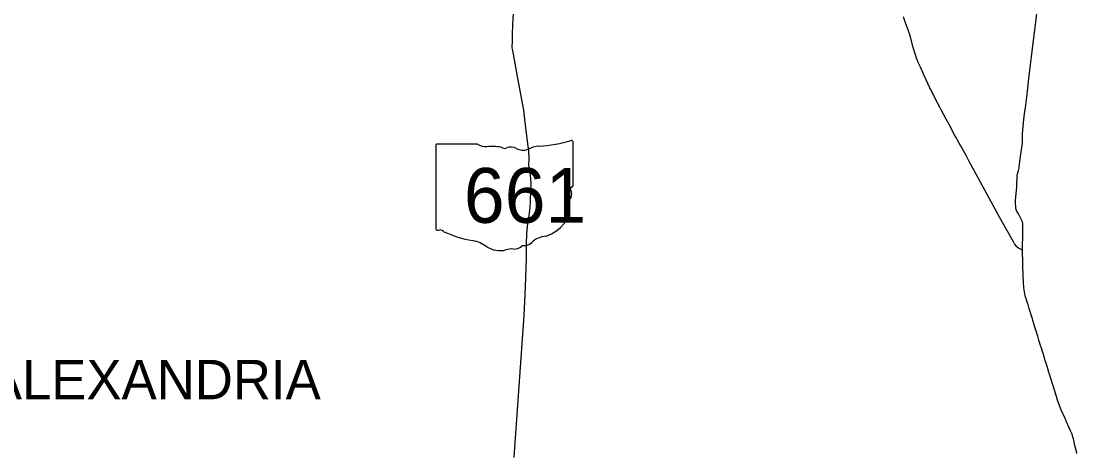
# Model space of a CAD drawing. Extents: x 1761803 to 2441803, y 509895 to 949895.
# Drawn here: x 1937717 to 1991282, y 855435 to 877258 of the extents above; entities that cross this region are included whole.
import ezdxf

# ---------------------------------------------------------------- set-up
doc = ezdxf.new("R2010")
doc.units = 0
for name, color, linetype in [('GM_X_County_Road', 7, 'Continuous'), ('GM_X_Minor_Lake', 7, 'Continuous'), ('GM_X_Township_Road', 7, 'Continuous')]:
    doc.layers.add(name, color=color, linetype=linetype)

msp = doc.modelspace()

# ---------------------------------------------------------------- linework, layer by layer
at = {"layer": 'GM_X_Minor_Lake'}
for points in [[(1962733, 855092), (1962787, 855848), (1963232, 862308), (1963289, 863375), (1963308, 863763), (1963353, 865210), (1963364, 866109), (1963370, 866280), (1963380, 866495), (1963424, 866974), (1963449, 867131), (1963484, 867276), (1963523, 867636), (1963539, 867818), (1963562, 868077), (1963563, 868104), (1963577, 868683), (1963587, 869010), (1963578, 869256), (1963564, 869433), (1963531, 869591), (1963506, 869702), (1963494, 869810), (1963483, 869947), (1963486, 870249), (1963474, 870679), (1963425, 871023), (1963276, 872269), (1963216, 872741), (1962908, 874444), (1962656, 875764), (1962645, 875833), (1962637, 875898), (1962636, 875990), (1962640, 876178), (1962654, 876557), (1962665, 877098), (1962695, 877619)], [(1983344, 874922), (1983342, 874926), (1983237, 875163), (1983193, 875259), (1983145, 875372), (1983103, 875491), (1983070, 875602), (1982978, 875923), (1982816, 876515), (1982784, 876622), (1982761, 876688), (1982716, 876821), (1982609, 877114), (1982480, 877466)], [(1988979, 875438), (1989228, 877495), (1989254, 877666)], [(1988847, 874350), (1988914, 874907), (1988979, 875438)], [(1983516, 874537), (1983479, 874620), (1983413, 874769), (1983344, 874922)], [(1983823, 873866), (1983538, 874489), (1983516, 874537)], [(1988313, 867464), (1988282, 867516), (1988236, 867597), (1988204, 867693), (1988186, 867769), (1988181, 867841), (1988168, 868004), (1988174, 868162), (1988227, 868826), (1988229, 868981), (1988244, 869331), (1988251, 869401), (1988260, 869455), (1988281, 869534), (1988308, 869627), (1988324, 869678), (1988345, 869813), (1988367, 870011), (1988402, 870261), (1988414, 870391), (1988439, 870504), (1988453, 870600), (1988478, 870728), (1988496, 870853), (1988518, 871022), (1988524, 871137), (1988530, 871227), (1988530, 871537), (1988535, 871715), (1988594, 872272), (1988643, 872663), (1988684, 872989), (1988737, 873390), (1988847, 874350)], [(1988066, 866049), (1987358, 867304), (1986190, 869456), (1986008, 869787), (1985905, 869970), (1985802, 870157), (1985760, 870234), (1985659, 870427), (1985387, 870921), (1985305, 871065), (1985210, 871242), (1985166, 871317), (1985076, 871480), (1984795, 872006), (1984657, 872270), (1984419, 872717), (1984344, 872859), (1984150, 873231), (1983985, 873548), (1983944, 873625), (1983866, 873777), (1983827, 873857), (1983823, 873866)], [(1988544, 866568), (1988537, 866947), (1988519, 867068), (1988492, 867141), (1988445, 867227), (1988353, 867397), (1988313, 867464)], [(1988520, 865620), (1988520, 865620), (1988544, 866546), (1988544, 866568)], [(1988118, 865956), (1988066, 866049)], [(1988236, 865798), (1988232, 865801), (1988144, 865909), (1988118, 865956)], [(1988520, 865620), (1988426, 865671), (1988325, 865723), (1988236, 865798)], [(1988530, 865310), (1988520, 865620)], [(1988532, 865259), (1988530, 865310)], [(1988545, 864743), (1988540, 865003), (1988532, 865259)], [(1988551, 864433), (1988545, 864743)], [(1988711, 863158), (1988666, 863303), (1988595, 863723), (1988553, 864331), (1988551, 864421), (1988551, 864433)], [(1988741, 863059), (1988711, 863158)], [(1988802, 862862), (1988780, 862931), (1988744, 863051), (1988741, 863059)], [(1988879, 862612), (1988866, 862652), (1988862, 862664), (1988822, 862794), (1988808, 862842), (1988802, 862862)], [(1988913, 862509), (1988912, 862511), (1988879, 862612)], [(1989025, 862145), (1988934, 862446), (1988913, 862509)], [(1989243, 861415), (1989134, 861768), (1989046, 862077), (1989025, 862145)], [(1989357, 861052), (1989293, 861256), (1989243, 861415)], [(1989455, 860741), (1989357, 861052)], [(1989536, 860481), (1989465, 860709), (1989455, 860741), (1989455, 860741)], [(1989568, 860377), (1989536, 860481)], [(1989680, 860013), (1989636, 860156), (1989568, 860377)], [(1989841, 859493), (1989818, 859559), (1989715, 859898), (1989680, 860013)], [(1990696, 857048), (1990682, 857080), (1990467, 857560), (1990303, 858010), (1990245, 858205), (1989876, 859390), (1989864, 859423), (1989841, 859493)], [(1990779, 856858), (1990696, 857048)], [(1990998, 856379), (1990964, 856459), (1990820, 856764), (1990779, 856858)], [(1991035, 856280), (1991010, 856352), (1990998, 856379)], [(1991176, 855716), (1991122, 855973), (1991041, 856264), (1991035, 856280)], [(1991245, 855457), (1991176, 855716)], [(1991282, 855301), (1991254, 855420), (1991245, 855457)]]:
    msp.add_lwpolyline(points, dxfattribs=at)
at = {"layer": 'GM_X_Township_Road'}
for p, q in [((1960864, 871017), (1958826, 871017)), ((1965718, 868911), (1965718, 871122)), ((1958757, 870944), (1958757, 866718)), ((1965717, 868911), (1965718, 868911))]:
    msp.add_line(p, q, dxfattribs=at)
for centre, major_axis, start_param, end_param in [((1958837, 870953), (80.6, 0), 1.712693, 3.28349), ((1961350, 871508), (782, 0), 4.042523, 4.731795), ((1963239, 876779), (7382, 0), 4.814394, 5.042369), ((1965641, 871131), (77.5, 0), 6.141152, 7.989035), ((1961609, 868644), (2808, 0), 1.404758, 1.657858), ((1962247, 870975), (226, 0), 3.836095, 5.185415), ((1962578, 870487), (469, 0), 0.950623, 2.079405), ((1963183, 871157), (564, 0), 4.081561, 5.145723), ((1964180, 869726), (1485, 0), 1.699011, 2.107814), ((1965700, 868749), (120, 0), 1.883978, 3.671073), ((1965635, 868902), (82.9, 0), 5.05454, 6.418171), ((1964937, 868469), (720, 0), 5.934695, 6.695948), ((1963652, 867704), (1846, 0), 5.101752, 6.440018), ((1965996, 867986), (524, 0), 2.387724, 3.262537), ((1958838, 866709), (81.4, 0), 3.00124, 4.508301), ((1958850, 867141), (621, 0), 4.665946, 4.897461), ((1958977, 866474), (224, 0), 0.519207, 1.627899), ((1961803, 870271), (5331, 0), 4.195997, 4.488961), ((1964431, 865531), (1011, 0), 1.647645, 2.488434), ((1960214, 864819), (1668, 0), 0.823519, 1.323587), ((1962018, 866453), (1058, 0), 4.026481, 4.996735), ((1962630, 864992), (870, 0), 1.495662, 1.94098), ((1962707, 866136), (564, 0), 4.691044, 5.507374), ((1963217, 865727), (159, 0), 1.147584, 2.315152), ((1963149, 866308), (597, 0), 4.937069, 5.64225)]:
    msp.add_ellipse(centre, major_axis=major_axis, ratio=0.8, start_param=start_param, end_param=end_param, dxfattribs=at)

# ---------------------------------------------------------------- texts
at = {"layer": 'GM_X_County_Road'}
msp.add_text('ALEXANDRIA', height=2000, rotation=0, dxfattribs=at).set_placement((1935975, 858058))
at = {"layer": 'GM_X_Township_Road'}
msp.add_text('661', height=2784.4, dxfattribs=at).set_placement((1960180, 867016))

doc.saveas('drawing.dxf')
